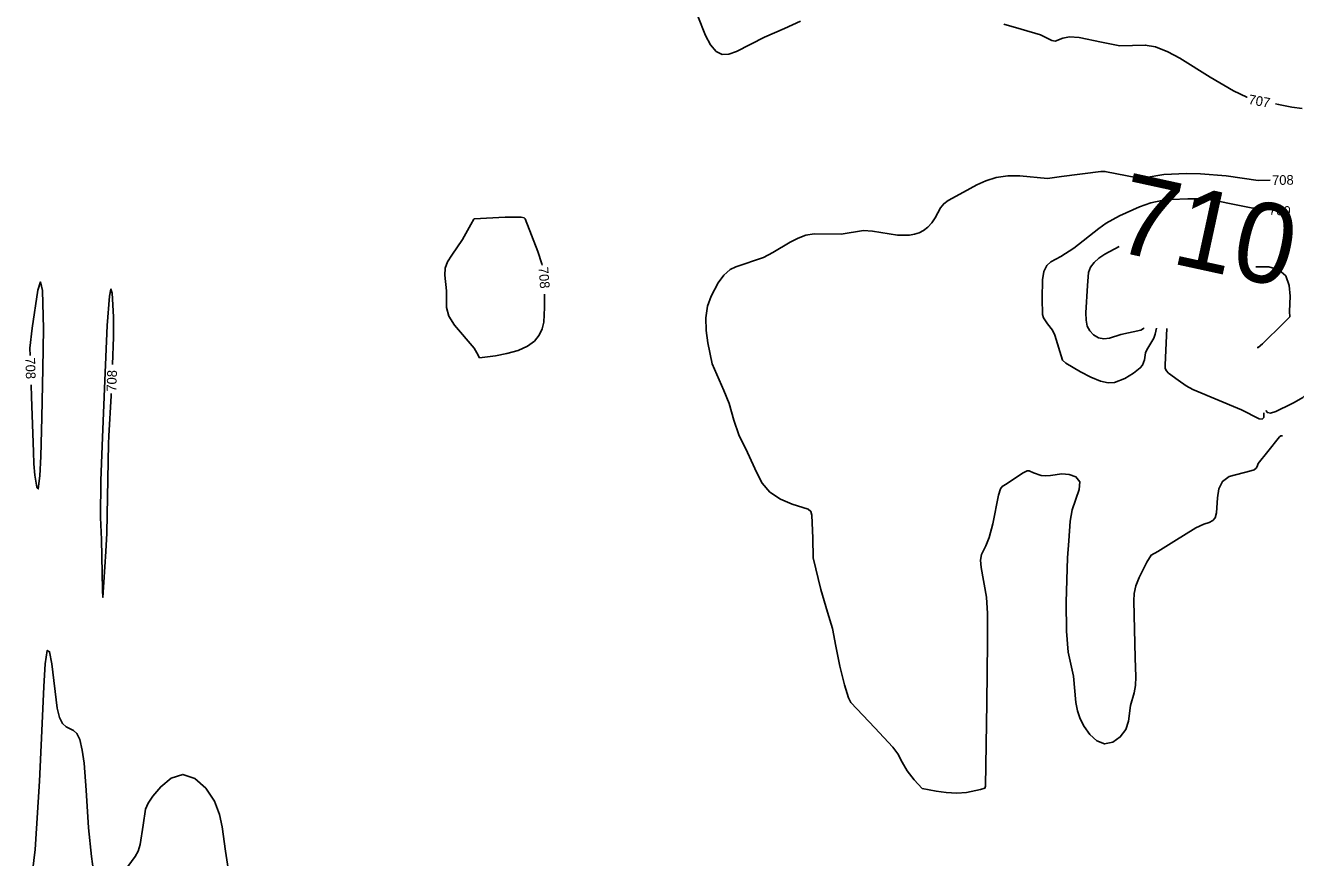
# Model space of a CAD drawing. Extents: x -291892836 to 2945206, y -477993085 to 1832792.
# Drawn here: x 1848595 to 1849119, y 544317 to 544659 of the extents above; entities that cross this region are included whole.
import ezdxf

# ---------------------------------------------------------------- set-up
doc = ezdxf.new("R2010")
doc.units = 0
doc.layers.add('DT_X_Contour_Minor', color=7, linetype='Continuous')
doc.layers.add('Level 19', color=7, linetype='Continuous')

msp = doc.modelspace()

# ---------------------------------------------------------------- linework, layer by layer
at = {"layer": 'DT_X_Contour_Minor'}
for points in [[(1848914.93, 544661.24), (1848908.29, 544658.27), (1848900.1, 544654.62), (1848888.49, 544648.68), (1848885.39, 544647.58), (1848882.66, 544647.47), (1848880.18, 544648.72), (1848877.85, 544651.51), (1848875.74, 544655.32), (1848872.52, 544663.32)], [(1849099.1, 544629.93), (1849098.96, 544629.97), (1849093.41, 544632.59), (1849083.87, 544638.14), (1849071.32, 544645.99), (1849066.33, 544648.66), (1849061.33, 544650.66), (1849057.02, 544651.38), (1849046.55, 544651.13), (1849038.93, 544652.62), (1849029.73, 544654.54), (1849025.81, 544654.82), (1849023.1, 544654.29), (1849019.91, 544652.96), (1849018.48, 544653.32), (1849013.83, 544655.61), (1849005.9, 544657.95), (1848998.71, 544659.98)], [(1849121.69, 544625.24), (1849117.53, 544625.85), (1849111.99, 544626.9), (1849110.79, 544627.11)], [(1848965.08, 544345.09), (1848961.73, 544348.61), (1848958.87, 544352.32), (1848956.8, 544355.95), (1848955.01, 544359.38), (1848952.99, 544362.06), (1848945.56, 544370.15), (1848935.63, 544380.46), (1848934.65, 544382.41), (1848933.02, 544387.8), (1848931.05, 544395.52), (1848929.46, 544403.71), (1848928.14, 544410.97), (1848926.02, 544417.7), (1848923.23, 544427.09), (1848920.11, 544440.17), (1848919.98, 544448.23), (1848919.55, 544457.72), (1848919.13, 544459.27), (1848918, 544460.12), (1848911.52, 544462.25), (1848906.71, 544464.29), (1848902.29, 544467.17), (1848899.1, 544470.9), (1848896.86, 544475.16), (1848893.07, 544483.58), (1848889.53, 544490.81), (1848887.45, 544496.88), (1848885.47, 544503.69), (1848883.26, 544509.08), (1848878.51, 544520.12), (1848876.73, 544528.64), (1848875.97, 544533.76), (1848875.8, 544539.06), (1848876.57, 544543.84), (1848877.99, 544547.9), (1848880.98, 544553.49), (1848883.31, 544556.54), (1848884.45, 544557.75), (1848885.96, 544558.88), (1848888.24, 544559.97), (1848899.58, 544563.9), (1848903.51, 544565.92), (1848910.62, 544570.23), (1848913.88, 544571.89), (1848917.13, 544573.03), (1848920.57, 544573.6), (1848931.66, 544573.44), (1848940.89, 544574.97), (1848944.52, 544574.72), (1848954.95, 544573.03), (1848959.77, 544573.08), (1848961.83, 544573.42), (1848963.77, 544574.03), (1848965.62, 544575), (1848967.39, 544576.41), (1848969.01, 544578.18), (1848970.4, 544580.18), (1848972.65, 544584.3), (1848973.97, 544586.02), (1848975.71, 544587.32), (1848982.13, 544590.72), (1848987.55, 544593.8), (1848991.26, 544595.43), (1848995.59, 544596.8), (1849000.35, 544597.57), (1849005.3, 544597.53), (1849016.72, 544596.47), (1849022.53, 544597.26), (1849038.75, 544599.33), (1849040.43, 544599.31), (1849053.85, 544596.75), (1849056.6, 544596.73), (1849064.76, 544598.03), (1849074.08, 544598.44), (1849079.79, 544598.4), (1849090.41, 544597.45), (1849103.6, 544595.59), (1849108.56, 544595.69)], [(1849107.37, 544583.62), (1849105.86, 544583.73), (1849100.75, 544584.36), (1849091.83, 544586.11), (1849085.13, 544587.53), (1849079.91, 544588.09), (1849074.55, 544588.02), (1849067.86, 544587.72), (1849063.84, 544587.3), (1849059.39, 544586.35), (1849054.62, 544584.72), (1849046.36, 544580.97), (1849040.94, 544578.04), (1849037.95, 544575.85), (1849027.54, 544567.7), (1849022.17, 544564.34), (1849018.12, 544562.12), (1849016.44, 544560.54), (1849015.23, 544558.12), (1849014.65, 544554.62), (1849014.51, 544546.91), (1849014.7, 544540.32), (1849015.14, 544538.94), (1849016.71, 544536.55), (1849018.76, 544533.91), (1849019.71, 544531.86), (1849022.89, 544521.62), (1849024.35, 544520.3), (1849030.37, 544516.74), (1849034.55, 544514.53), (1849038.56, 544512.85), (1849041.78, 544512.2), (1849044.33, 544512.41), (1849048.57, 544514.02), (1849052.22, 544516.14), (1849054.95, 544518.38), (1849055.85, 544519.5), (1849056.69, 544521.65), (1849057.11, 544524.57), (1849057.63, 544525.77), (1849060.62, 544530.61), (1849061.15, 544532.21), (1849061.61, 544534.76)], [(1848808.31, 544560.71), (1848808.2, 544561.24), (1848806.64, 544566.28), (1848801.43, 544579.8), (1848800.93, 544580.19), (1848799.71, 544580.44), (1848793.07, 544580.45), (1848780.36, 544579.81), (1848780.14, 544579.65), (1848778.91, 544577.47), (1848775.48, 544571.25), (1848771.17, 544564.79), (1848769.41, 544562.14), (1848768.37, 544559.49), (1848768.24, 544556.57), (1848768.92, 544550.11), (1848768.9, 544543.3), (1848769.88, 544539.69), (1848772.26, 544535.94), (1848780.31, 544526.5), (1848781.47, 544524.63), (1848782.48, 544522.49)], [(1849056.55, 544534.89), (1849056.32, 544534.57), (1849055.22, 544533.95), (1849046.9, 544532.13), (1849042.24, 544530.57), (1849039.98, 544530.33), (1849037.76, 544530.83), (1849035.73, 544531.99), (1849034.14, 544533.63), (1849033.12, 544535.63), (1849032.62, 544538.07), (1849032.51, 544541.1), (1849033.17, 544552.26), (1849033.68, 544557.7), (1849034.46, 544559.82), (1849035.91, 544561.77), (1849037.92, 544563.58), (1849040.34, 544565.22), (1849046.31, 544568.39)], [(1849137.25, 544567.23), (1849141.03, 544566.48), (1849142.29, 544566.71), (1849143.59, 544565.25), (1849144.87, 544563.46), (1849144.94, 544562.44), (1849144.14, 544561.24), (1849136.91, 544547.99), (1849136.28, 544546.32), (1849135.07, 544540.01), (1849132.81, 544528.04), (1849128.76, 544517.74), (1849125.43, 544510.36), (1849124.01, 544508.09), (1849121.96, 544506.14), (1849118.46, 544504.19), (1849117.38, 544503.62)], [(1849103.23, 544526.74), (1849103.65, 544526.8), (1849105.36, 544528.34), (1849113.98, 544536.76), (1849116.63, 544539.42), (1849116.54, 544541.61), (1849116.75, 544547.96), (1849116.44, 544552.38), (1849115.05, 544556.29), (1849112.15, 544558.83), (1849107.95, 544560), (1849102.85, 544560.02), (1849102.67, 544559.99)], [(1848597.26, 544523.46), (1848597.16, 544526.54), (1848598.06, 544534.74), (1848600.47, 544550.39), (1848601.6, 544553.77), (1848602.29, 544550.29), (1848602.71, 544534.48), (1848602.52, 544518.12), (1848602.03, 544497.95), (1848601.63, 544481.92)], [(1848628.92, 544450.25), (1848628.48, 544442.68), (1848627.24, 544423.82), (1848627.06, 544426.98), (1848626.72, 544447.67), (1848626.31, 544456.77), (1848626.39, 544471.96), (1848627.05, 544489.64), (1848628.05, 544513.16), (1848629.01, 544535.86), (1848630.03, 544547.89), (1848630.58, 544550.83), (1848631.05, 544549.14), (1848631.61, 544539.43), (1848631.6, 544531.07), (1848631.17, 544519.82)], [(1848782.48, 544522.49), (1848789.13, 544523.4), (1848793.82, 544524.26), (1848798.48, 544525.54), (1848802.31, 544527.3), (1848805.18, 544529.44), (1848807.17, 544531.87), (1848808.38, 544534.49), (1848809, 544537.27), (1848809.4, 544543.21), (1848809.4, 544548.76)], [(1849065.91, 544534.65), (1849065.28, 544519.65), (1849065.31, 544518.23), (1849065.65, 544517.26), (1849066.64, 544516.23), (1849070.61, 544513.27), (1849073.92, 544510.98)], [(1848601.63, 544481.92), (1848601.25, 544473.85), (1848600.58, 544468.53), (1848600.08, 544469.18), (1848599.17, 544474.12), (1848598.85, 544478.83), (1848598.65, 544483.84), (1848597.78, 544506.48), (1848597.62, 544511.47)], [(1848630.71, 544507.83), (1848630.68, 544506.91), (1848629.77, 544490.43), (1848629.56, 544487.1), (1848629.03, 544457.83), (1848628.92, 544450.25)], [(1849073.92, 544510.98), (1849076.6, 544509.44), (1849096.71, 544501.06), (1849104.07, 544497.46), (1849105.29, 544497.31), (1849105.87, 544497.89), (1849105.92, 544499.84)], [(1849117.38, 544503.62), (1849110.94, 544500.44), (1849108.72, 544499.78), (1849107.39, 544500), (1849106.81, 544500.78)], [(1849113.6, 544490.4), (1849112.98, 544490.41), (1849112.35, 544489.91), (1849107.53, 544483.93), (1849103.63, 544478.94), (1849103.21, 544477.72), (1849102.72, 544477.04), (1849101.91, 544476.45), (1849100.52, 544475.93), (1849091.63, 544473.6), (1849088.85, 544471.59), (1849087.38, 544468.49), (1849086.89, 544464.83), (1849086.44, 544458.6), (1849085.82, 544456.67), (1849084.84, 544455.44), (1849083.39, 544454.74), (1849081.19, 544453.98), (1849077.93, 544452.5), (1849068.79, 544446.83), (1849062.2, 544442.73), (1849059.5, 544441.25), (1849057.69, 544438.34), (1849054.54, 544432.08), (1849053.22, 544428.6), (1849052.52, 544425.45), (1849052.31, 544422.43), (1849052.87, 544398.93), (1849053.19, 544391.16), (1849053.02, 544387.49), (1849052.44, 544384.5), (1849051.02, 544379.23), (1849050.18, 544372.82), (1849048.99, 544369.44), (1849046.7, 544366.36), (1849043.64, 544364.14), (1849040.28, 544363.45), (1849037.07, 544364.7), (1849034.21, 544367.34), (1849031.88, 544370.6), (1849030.21, 544373.84), (1849029.1, 544377.09), (1849028.44, 544380.48), (1849027.46, 544391.36), (1849025.31, 544401.28), (1849024.58, 544409.92), (1849024.42, 544421.82), (1849025.01, 544440.16), (1849025.54, 544447.12), (1849026.04, 544455.23), (1849026.94, 544459.84), (1849029.84, 544468.32), (1849030.07, 544471.46), (1849028.47, 544473.48), (1849025.68, 544474.51), (1849022.62, 544474.77), (1849017.94, 544474.11), (1849016.04, 544473.85), (1849014.16, 544474.02), (1849010.99, 544475.09), (1849009.16, 544475.92), (1849008.39, 544475.95), (1849006.37, 544474.99), (1849000.09, 544470.74), (1848998.08, 544469.54), (1848997.37, 544468.52), (1848996.5, 544465.89), (1848994.19, 544454.16), (1848992.72, 544448.51), (1848991.26, 544445.01), (1848989.54, 544441.5), (1848989.16, 544439.11), (1848989.39, 544436.1), (1848991.62, 544423.94), (1848992.05, 544417.17), (1848992.05, 544405.39), (1848991.7, 544380.35), (1848991.19, 544346.02), (1848990.95, 544345.25), (1848989.08, 544344.64), (1848983.35, 544343.47), (1848979.32, 544343.21), (1848974.92, 544343.48), (1848970.76, 544344.05), (1848965.08, 544345.09)], [(1848598.23, 544310.86), (1848599.37, 544319.94), (1848601.11, 544348.05), (1848602.05, 544368.88), (1848602.86, 544387.05), (1848603.51, 544396.42), (1848604.32, 544401.96), (1848605.26, 544401.44), (1848606.22, 544396.5), (1848608.43, 544378.23), (1848609.32, 544374.32), (1848610.56, 544371.84), (1848612.06, 544370.46), (1848615.15, 544369.05), (1848616.53, 544367.81), (1848617.74, 544365.27), (1848618.75, 544360.94), (1848619.54, 544355.47), (1848620.42, 544344.41), (1848621.29, 544328.93), (1848622.51, 544317.02), (1848624.22, 544305.04)], [(1848630.35, 544303.16), (1848640.59, 544317.02), (1848641.84, 544319.27), (1848642.69, 544321.99), (1848643.87, 544329.96), (1848644.88, 544336.62), (1848645.89, 544339.08), (1848647.86, 544342), (1848651.12, 544345.84), (1848655.39, 544349.36), (1848660.23, 544350.9), (1848665.2, 544349.28), (1848669.74, 544345.22), (1848673.27, 544339.89), (1848675.4, 544334.38), (1848676.44, 544329.34), (1848677.87, 544319.31), (1848679.92, 544305.94)]]:
    msp.add_lwpolyline(points, dxfattribs=at)

# ---------------------------------------------------------------- texts
at = {"layer": 'Level 19'}
for s, height, rotation, p in [('707', 4, 349.8881, (1849099.35, 544627.12)), ('710', 33, 347.7395, (1849043.14, 544566.83)), ('708', 4, 1.1516, (1849109.35, 544593.7)), ('709', 4, 355.7495, (1849107.96, 544581.57)), ('708', 4, 274.8536, (1848806.82, 544559.83)), ('708', 4, 271.7482, (1848595.28, 544522.64)), ('708', 4, 87.823, (1848632.74, 544508.51))]:
    msp.add_text(s, height=height, rotation=rotation, dxfattribs=at).set_placement(p)

doc.saveas('drawing.dxf')
